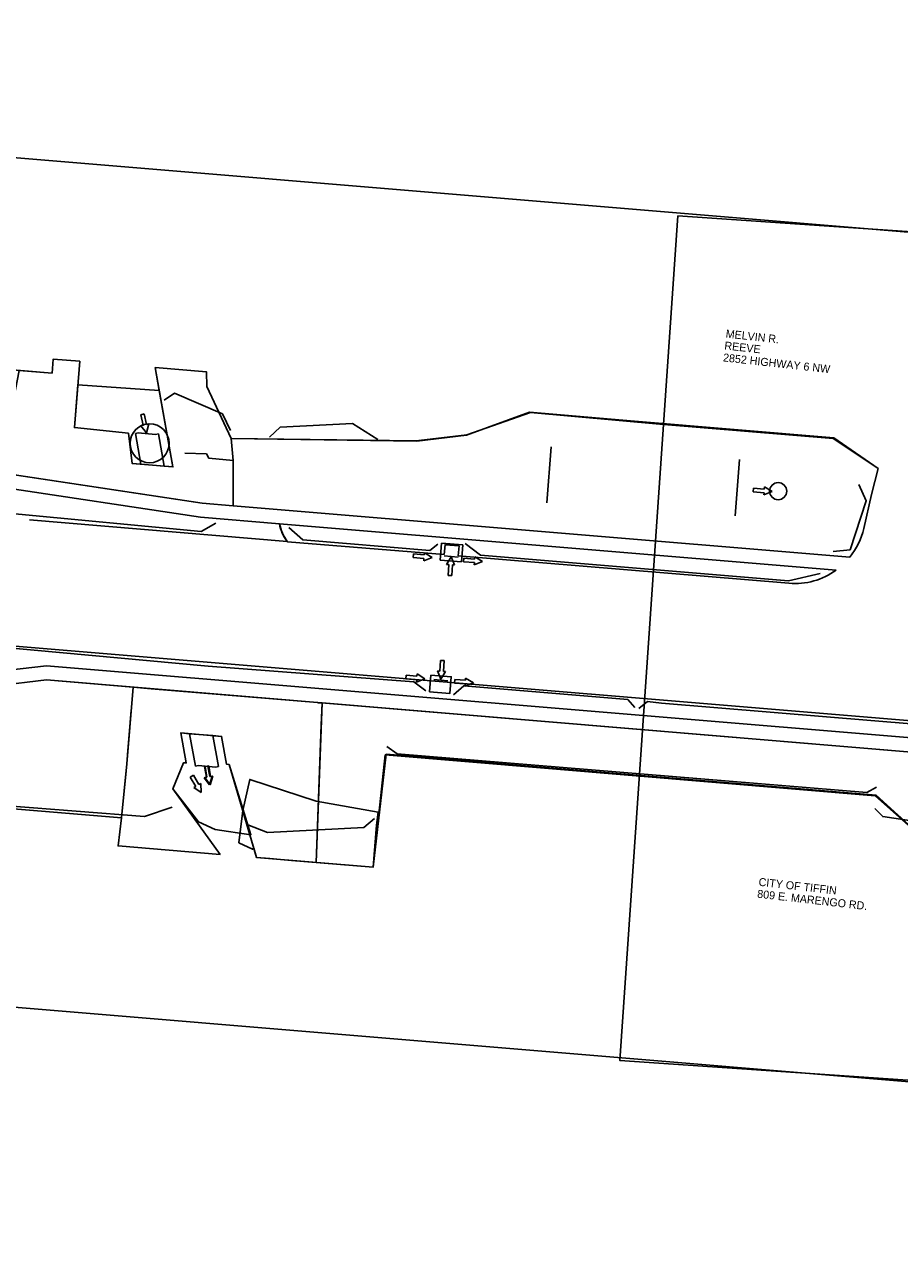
# Model space of a CAD drawing. Extents: x 20499990 to 20505779, y 7953198 to 7954399.
# Drawn here: x 20503807.3 to 20504117.2, y 7953486.1 to 7953917.4 of the extents above; entities that cross this region are included whole.
import ezdxf

# ---------------------------------------------------------------- set-up
doc = ezdxf.new("R2010")
doc.units = 0
for name, color, linetype in [('Building', 7, 'Continuous'), ('ClearGrub', 7, 'Continuous'), ('dsnCellElements', 7, 'Continuous'), ('ErosionControl', 7, 'Continuous'), ('NamedBoundary', 7, 'Continuous'), ('Seeding', 7, 'Continuous'), ('Text', 7, 'Continuous')]:
    doc.layers.add(name, color=color, linetype=linetype)

msp = doc.modelspace()

# ---------------------------------------------------------------- linework, layer by layer
at = {"layer": 'Building'}
for p, q in [((20503869.7, 7953742.74), (20503631.86, 7953778.64)), ((20503880.46, 7953770.66), (20503881.17, 7953762.87)), ((20503881.17, 7953762.87), (20503881.17, 7953746.8)), ((20503881.17, 7953746.8), (20504099.61, 7953728.58)), ((20503809.08, 7953741.78), (20503900.39, 7953734.16)), ((20503897.62, 7953740.41), (20503869.7, 7953742.74)), ((20503897.62, 7953740.41), (20504094.74, 7953723.96)), ((20503955.95, 7953729.53), (20503900.49, 7953734.03)), ((20504078.05, 7953719.34), (20503960.93, 7953729.11)), ((20503625.39, 7953668.38), (20503815.08, 7953690.11)), ((20503815.08, 7953690.11), (20504247.14, 7953654.05)), ((20503815.16, 7953685.08), (20503635.14, 7953664.47)), ((20503845.78, 7953682.53), (20503815.16, 7953685.08)), ((20503845.07, 7953673.92), (20503845.78, 7953682.53)), ((20504142.52, 7953657.76), (20503912.79, 7953676.94)), ((20503844.4, 7953665.62), (20503844.99, 7953672.96)), ((20503845.07, 7953673.92), (20503845.07, 7953673.92)), ((20503845.07, 7953673.92), (20503845.07, 7953673.92)), ((20503935.36, 7953658.74), (20503935.36, 7953658.74)), ((20503935.36, 7953658.74), (20503935.36, 7953658.74)), ((20503935.36, 7953658.74), (20503935.36, 7953658.74))]:
    msp.add_line(p, q, dxfattribs=at)
for points in [[(20504109.65, 7953759.97), (20504093.91, 7953770.89), (20504023.3, 7953776.79), (20503986.14, 7953780), (20503963.88, 7953771.82), (20503946.28, 7953769.64), (20503880.46, 7953770.66)], [(20504104.51, 7953738.74), (20504107.23, 7953750.76), (20504109.65, 7953759.97)], [(20504427.73, 7953645), (20504246.09, 7953660.16), (20503289.64, 7953739.98)], [(20503960.93, 7953729.11), (20503961.22, 7953732.6), (20503956.24, 7953733.01), (20503955.95, 7953729.53)], [(20503372.47, 7953675.36), (20503841.67, 7953636.21)], [(20503912.79, 7953676.94), (20503910.63, 7953620.42), (20503930.78, 7953618.73), (20503935.36, 7953658.74)], [(20503843.94, 7953660.06), (20503844.4, 7953665.62)], [(20503843.56, 7953655.35), (20503843.94, 7953660.06)], [(20503935.36, 7953658.74), (20503935.36, 7953658.74)], [(20503935.36, 7953658.74), (20503935.36, 7953658.74)], [(20503935.36, 7953658.74), (20503935.36, 7953658.74), (20504108.89, 7953644.26), (20504139.58, 7953616.36), (20504141.32, 7953644.33)], [(20503843.06, 7953650.36), (20503843.56, 7953655.35)], [(20503841.67, 7953636.21), (20503843.06, 7953650.36)]]:
    msp.add_lwpolyline(points, dxfattribs=at)
for centre, radius, start, end in [((20503912.74, 7953743.37), 15.4, 191.0582, 216.7042), ((20503911.41, 7953742.77), 13.99, 189.7033, 218.6642), ((20504080.13, 7953744.25), 25, 321.1743, 347.268), ((20504080.13, 7953744.25), 25, 265.2301, 305.7659), ((20503873.4, 7953671.13), 28.46, 174.3633, 176.3018)]:
    msp.add_arc(centre, radius, start, end, dxfattribs=at)
at = {"layer": 'ClearGrub'}
msp.add_lwpolyline([(20503910.61, 7953642.15), (20503932.58, 7953638.18), (20503932.03, 7953633.68), (20503930.78, 7953618.73), (20503901.88, 7953621.15), (20503897.94, 7953621.47), (20503894.2, 7953621.79), (20503889.46, 7953622.18), (20503888.51, 7953625.46), (20503888.01, 7953625.1), (20503883.27, 7953627.4), (20503884.67, 7953638.82), (20503887.1, 7953649.86)], close=True, dxfattribs=at)
at = {"layer": 'dsnCellElements'}
for p, q in [((20503848.48, 7953779.04), (20503849.72, 7953779.32)), ((20503848.48, 7953779.04), (20503849.72, 7953779.32)), ((20503849.32, 7953775.32), (20503848.48, 7953779.04)), ((20503849.32, 7953775.32), (20503848.48, 7953779.04)), ((20503849.72, 7953779.32), (20503850.56, 7953775.59)), ((20503849.72, 7953779.32), (20503850.56, 7953775.59)), ((20503848.54, 7953775.14), (20503849.32, 7953775.32)), ((20503848.54, 7953775.14), (20503849.32, 7953775.32)), ((20503850.57, 7953772.66), (20503848.54, 7953775.14)), ((20503850.57, 7953772.66), (20503848.54, 7953775.14)), ((20503850.56, 7953775.59), (20503851.34, 7953775.77)), ((20503850.56, 7953775.59), (20503851.34, 7953775.77)), ((20503851.34, 7953775.77), (20503850.57, 7953772.66)), ((20503851.34, 7953775.77), (20503850.57, 7953772.66)), ((20504065.4, 7953751.71), (20504065.5, 7953752.98)), ((20504065.5, 7953752.98), (20504069.3, 7953752.7)), ((20504069.3, 7953752.7), (20504069.36, 7953753.49)), ((20504069.36, 7953753.49), (20504072.11, 7953751.85)), ((20504069.21, 7953751.43), (20504065.4, 7953751.71)), ((20504072.11, 7953751.85), (20504069.15, 7953750.63)), ((20504069.15, 7953750.63), (20504069.21, 7953751.43)), ((20503944.96, 7953728.46), (20503945.08, 7953729.73)), ((20503948.76, 7953728.11), (20503944.96, 7953728.46)), ((20503945.08, 7953729.73), (20503948.88, 7953729.38)), ((20503951.67, 7953728.48), (20503948.69, 7953727.32)), ((20503948.69, 7953727.32), (20503948.76, 7953728.11)), ((20503948.88, 7953729.38), (20503948.95, 7953730.17)), ((20503948.95, 7953730.17), (20503951.67, 7953728.48)), ((20503956.8, 7953726.01), (20503958.42, 7953728.76)), ((20503958.42, 7953728.76), (20503959.65, 7953725.81)), ((20503962.84, 7953726.93), (20503962.94, 7953728.2)), ((20503966.65, 7953726.65), (20503962.84, 7953726.93)), ((20503962.94, 7953728.2), (20503966.74, 7953727.91)), ((20503969.55, 7953727.07), (20503966.59, 7953725.85)), ((20503966.59, 7953725.85), (20503966.65, 7953726.65)), ((20503966.74, 7953727.91), (20503966.8, 7953728.71)), ((20503966.8, 7953728.71), (20503969.55, 7953727.07)), ((20503957.59, 7953725.95), (20503956.8, 7953726.01)), ((20503957.33, 7953722.14), (20503957.59, 7953725.95)), ((20503958.6, 7953722.06), (20503957.33, 7953722.14)), ((20503958.86, 7953725.87), (20503958.6, 7953722.06)), ((20503959.65, 7953725.81), (20503958.86, 7953725.87)), ((20503954.39, 7953688.22), (20503954.67, 7953692.02)), ((20503954.67, 7953692.02), (20503955.94, 7953691.93)), ((20503955.94, 7953691.93), (20503955.66, 7953688.12)), ((20503954.81, 7953685.32), (20503953.6, 7953688.28)), ((20503953.6, 7953688.28), (20503954.39, 7953688.22)), ((20503956.45, 7953688.06), (20503954.81, 7953685.32)), ((20503955.66, 7953688.12), (20503956.45, 7953688.06)), ((20503942.42, 7953685.45), (20503942.52, 7953686.72)), ((20503946.22, 7953685.13), (20503942.42, 7953685.45)), ((20503942.52, 7953686.72), (20503946.32, 7953686.4)), ((20503949.12, 7953685.53), (20503946.15, 7953684.34)), ((20503946.15, 7953684.34), (20503946.22, 7953685.13)), ((20503946.32, 7953686.4), (20503946.39, 7953687.2)), ((20503946.39, 7953687.2), (20503949.12, 7953685.53)), ((20503959.56, 7953683.97), (20503959.66, 7953685.24)), ((20503963.37, 7953683.69), (20503959.56, 7953683.97)), ((20503959.66, 7953685.24), (20503963.47, 7953684.96)), ((20503966.27, 7953684.11), (20503963.31, 7953682.89)), ((20503963.31, 7953682.89), (20503963.37, 7953683.69)), ((20503963.47, 7953684.96), (20503963.52, 7953685.75)), ((20503963.52, 7953685.75), (20503966.27, 7953684.11)), ((20503871.05, 7953654.36), (20503872.3, 7953654.59)), ((20503871.73, 7953650.61), (20503871.05, 7953654.36)), ((20503871.34, 7953654.41), (20503872.59, 7953654.61)), ((20503871.94, 7953650.64), (20503871.34, 7953654.41)), ((20503872.3, 7953654.59), (20503872.98, 7953650.83)), ((20503872.59, 7953654.61), (20503873.2, 7953650.85)), ((20503866.04, 7953650.68), (20503867.14, 7953651.32)), ((20503867.95, 7953647.38), (20503866.04, 7953650.68)), ((20503867.14, 7953651.32), (20503869.05, 7953648.01)), ((20503870.95, 7953650.46), (20503871.73, 7953650.61)), ((20503872.87, 7953647.9), (20503870.95, 7953650.46)), ((20503871.16, 7953650.52), (20503871.94, 7953650.64)), ((20503873.02, 7953647.92), (20503871.16, 7953650.52)), ((20503873.77, 7953650.98), (20503872.87, 7953647.9)), ((20503872.98, 7953650.83), (20503873.77, 7953650.98)), ((20503873.98, 7953650.97), (20503873.02, 7953647.92)), ((20503873.2, 7953650.85), (20503873.98, 7953650.97)), ((20503867.26, 7953646.98), (20503867.95, 7953647.38)), ((20503869.93, 7953645.22), (20503867.26, 7953646.98)), ((20503869.05, 7953648.01), (20503869.74, 7953648.41)), ((20503869.74, 7953648.41), (20503869.93, 7953645.22))]:
    msp.add_line(p, q, dxfattribs=at)
at = {"layer": 'ErosionControl'}
for p, q in [((20503855.01, 7953787.67), (20503826.26, 7953789.65)), ((20503859.9, 7953760.55), (20503855.01, 7953787.67)), ((20503848.56, 7953761.5), (20503846.58, 7953772.44)), ((20503854.74, 7953772.28), (20503856.81, 7953760.81)), ((20503881.17, 7953762.87), (20503880.46, 7953770.66)), ((20503992.26, 7953747.78), (20503993.79, 7953767.72)), ((20503845.46, 7953761.75), (20503848.56, 7953761.5)), ((20503848.56, 7953761.5), (20503856.81, 7953760.81)), ((20503881.24, 7953746.8), (20503881.17, 7953762.87)), ((20504059.04, 7953743.25), (20504060.57, 7953763.19)), ((20503800.57, 7953758.23), (20503870.28, 7953747.71)), ((20503856.81, 7953760.81), (20503859.9, 7953760.55)), ((20503856.81, 7953760.81), (20503859.9, 7953760.55)), ((20503870.28, 7953747.71), (20503881.24, 7953746.8)), ((20503960.89, 7953728.61), (20503955.91, 7953729.03)), ((20503952.26, 7953685.2), (20503957.24, 7953684.8)), ((20503845.78, 7953682.53), (20503843.56, 7953655.35)), ((20503852.24, 7953681.99), (20503845.78, 7953682.53)), ((20503845.78, 7953682.53), (20503845.78, 7953682.53)), ((20503911.07, 7953677.08), (20503852.24, 7953681.99)), ((20503911.07, 7953677.08), (20503911.07, 7953677.08)), ((20503911.07, 7953677.08), (20503911.07, 7953677.08)), ((20503911.07, 7953677.08), (20503911.07, 7953677.08)), ((20503912.44, 7953669.15), (20503912.79, 7953676.94)), ((20503862.69, 7953666.3), (20503865.78, 7953666.04)), ((20503865.78, 7953666.04), (20503862.69, 7953666.3)), ((20503862.69, 7953666.3), (20503865.78, 7953666.04)), ((20503865.78, 7953666.04), (20503867.85, 7953654.57)), ((20503874.04, 7953665.35), (20503865.78, 7953666.04)), ((20503865.78, 7953666.04), (20503867.85, 7953654.57)), ((20503876.01, 7953654.41), (20503874.04, 7953665.35)), ((20503874.04, 7953665.35), (20503877.13, 7953665.09)), ((20503876.01, 7953654.41), (20503874.04, 7953665.35)), ((20503874.04, 7953665.35), (20503877.13, 7953665.09)), ((20503843.56, 7953655.37), (20503843.56, 7953655.35))]:
    msp.add_line(p, q, dxfattribs=at)
for points in [[(20503826.97, 7953797.99), (20503817.52, 7953798.78), (20503817.1, 7953793.79), (20503805.48, 7953794.76), (20503803, 7953781.9), (20503802.76, 7953774.63), (20503802.16, 7953770.12)], [(20503855.01, 7953787.67), (20503859.9, 7953760.55), (20503845.46, 7953761.75), (20503844.1, 7953772.5), (20503824.99, 7953774.5), (20503826.97, 7953797.99)], [(20503880.46, 7953770.66), (20503871.92, 7953789.05), (20503871.77, 7953794.25), (20503853.64, 7953795.76), (20503855.01, 7953787.67)], [(20503859.9, 7953760.55), (20503855.01, 7953787.67), (20503826.26, 7953789.65), (20503824.99, 7953774.5), (20503844.1, 7953772.5), (20503845.46, 7953761.75), (20503848.56, 7953761.5)], [(20503826.26, 7953789.65), (20503824.99, 7953774.5), (20503844.1, 7953772.5), (20503845.46, 7953761.75)], [(20503856.78, 7953784.24), (20503860.5, 7953786.67), (20503877.39, 7953779.37), (20503880.26, 7953773.5)], [(20503894.14, 7953771.06), (20503897.86, 7953774.64), (20503923.5, 7953775.96), (20503932.4, 7953770.26)], [(20503846.58, 7953772.44), (20503847.57, 7953772.62), (20503853.76, 7953772.1), (20503854.74, 7953772.28)], [(20503881.17, 7953762.87), (20503872.61, 7953763.61), (20503871.73, 7953765.14), (20503864.1, 7953765.45)], [(20504093.66, 7953730.6), (20504099.7, 7953731.21), (20504105.4, 7953748.53), (20504102.82, 7953754.31)], [(20503799, 7953747.79), (20503802.78, 7953744.01), (20503869.88, 7953737.71), (20503875.04, 7953740.68)], [(20503900.91, 7953739.08), (20503905.84, 7953734.73), (20503950.84, 7953730.95), (20503953.7, 7953733.24)], [(20503963.32, 7953733.47), (20503968.82, 7953729.34), (20504077.83, 7953720.18), (20504089.05, 7953722.82)], [(20503949.49, 7953681.28), (20503945.16, 7953684.46), (20503872.39, 7953690.02), (20503799.21, 7953696.72), (20503792.9, 7953695.34)], [(20504023.41, 7953675.28), (20504020.94, 7953678.19), (20503962.9, 7953682.96), (20503959.19, 7953679.78)], [(20504159.22, 7953663.7), (20504155.57, 7953666.68), (20504091.33, 7953672.01), (20504032.85, 7953676.87), (20504027.91, 7953677.4), (20504024.82, 7953675.01)], [(20503868.94, 7953634.85), (20503859.82, 7953646.47), (20503863.61, 7953655.66), (20503864.6, 7953655.7), (20503862.69, 7953666.3)], [(20503862.69, 7953666.3), (20503864.6, 7953655.7), (20503863.61, 7953655.66), (20503859.82, 7953646.47), (20503868.94, 7953634.85), (20503874.87, 7953632.12), (20503887.49, 7953630.23), (20503879.79, 7953655.09), (20503878.91, 7953655.22), (20503877.13, 7953665.09), (20503874.04, 7953665.35)], [(20503868.94, 7953634.85), (20503859.82, 7953646.47), (20503863.61, 7953655.66), (20503864.6, 7953655.7), (20503862.69, 7953666.3)], [(20503876.58, 7953623.26), (20503859.82, 7953646.47), (20503863.61, 7953655.66), (20503864.6, 7953655.7), (20503862.69, 7953666.3), (20503877.13, 7953665.09), (20503878.91, 7953655.22), (20503879.79, 7953655.09), (20503889.46, 7953622.18)], [(20503912.11, 7953662.68), (20503912.44, 7953669.15)], [(20503877.13, 7953665.09), (20503878.91, 7953655.22), (20503879.79, 7953655.09), (20503887.49, 7953630.23)], [(20503877.13, 7953665.09), (20503878.91, 7953655.22), (20503879.79, 7953655.09), (20503887.49, 7953630.23)], [(20503889.46, 7953622.18), (20503910.63, 7953620.42), (20503912.11, 7953662.68)], [(20503912.11, 7953662.68), (20503912.11, 7953662.68)], [(20503935.65, 7953661.47), (20503939.24, 7953658.92), (20504105.65, 7953645.17), (20504109.07, 7953647.15)], [(20503843.56, 7953655.35), (20503841.67, 7953636.21), (20503840.45, 7953626.27), (20503876.58, 7953623.26)], [(20503867.85, 7953654.57), (20503868.84, 7953654.74), (20503875.03, 7953654.23), (20503876.01, 7953654.41)], [(20503867.85, 7953654.57), (20503868.84, 7953654.74), (20503875.03, 7953654.23), (20503876.01, 7953654.41)], [(20503723.64, 7953649.88), (20503728.66, 7953646.17), (20503849.78, 7953636.69), (20503859.63, 7953640.03)], [(20503886.38, 7953633.79), (20503893.35, 7953630.98), (20503927.47, 7953632.82), (20503931.25, 7953635.98)], [(20504108.45, 7953639.59), (20504111.27, 7953636.67), (20504127.63, 7953634.23), (20504133.38, 7953636.08)], [(20503887.49, 7953630.23), (20503874.87, 7953632.12), (20503868.94, 7953634.85)], [(20503887.49, 7953630.23), (20503874.87, 7953632.12), (20503868.94, 7953634.85)]]:
    msp.add_lwpolyline(points, dxfattribs=at)
for points in [[(20503955, 7953733.54), (20503954.53, 7953727.56), (20503962.07, 7953726.96), (20503962.55, 7953732.94)], [(20503951.24, 7953686.78), (20503958.47, 7953686.21), (20503958, 7953680.31), (20503950.78, 7953680.88)]]:
    msp.add_lwpolyline(points, close=True, dxfattribs=at)
for centre, radius in [((20503851.64, 7953768.93), 6.92), ((20504074.22, 7953751.96), 3.04)]:
    msp.add_circle(centre, radius, dxfattribs=at)
msp.add_arc((20503913.17, 7953691.85), 14.92, 261.9009, 268.5586, dxfattribs=at)
at = {"layer": 'NamedBoundary'}
for points in [[(20503238.22, 7953917.37), (20503213.27, 7953618.41), (20504150.52, 7953540.19), (20504175.47, 7953839.15)], [(20504038.63, 7953849.54), (20504018.15, 7953550.24), (20504956.36, 7953486.07), (20504976.83, 7953785.37)]]:
    msp.add_lwpolyline(points, close=True, dxfattribs=at)
at = {"layer": 'Seeding'}
for p, q in [((20503632.44, 7953783.61), (20503870.28, 7953747.71)), ((20503869.7, 7953742.74), (20503631.86, 7953778.64)), ((20503881.17, 7953762.87), (20503880.46, 7953770.66)), ((20503880.46, 7953770.66), (20503881.17, 7953762.87)), ((20503848.56, 7953761.5), (20503856.81, 7953760.81)), ((20503881.24, 7953746.8), (20503881.17, 7953762.87)), ((20503881.17, 7953762.87), (20503881.17, 7953746.8)), ((20503856.81, 7953760.81), (20503859.9, 7953760.55)), ((20503870.28, 7953747.71), (20503881.24, 7953746.8)), ((20503881.17, 7953746.8), (20504099.61, 7953728.58)), ((20503809.08, 7953741.78), (20503900.39, 7953734.16)), ((20503897.62, 7953740.41), (20503869.7, 7953742.74)), ((20503897.62, 7953740.41), (20504094.74, 7953723.96)), ((20503955.95, 7953729.53), (20503900.49, 7953734.03)), ((20504078.05, 7953719.34), (20503960.93, 7953729.11)), ((20503625.39, 7953668.38), (20503815.08, 7953690.11)), ((20503815.08, 7953690.11), (20504247.14, 7953654.05)), ((20503815.16, 7953685.08), (20503635.14, 7953664.47)), ((20504246.23, 7953649.11), (20503815.16, 7953685.08))]:
    msp.add_line(p, q, dxfattribs=at)
for points in [[(20503826.97, 7953797.99), (20503817.52, 7953798.78), (20503817.1, 7953793.79), (20503740.06, 7953800.22), (20503714.23, 7953802.38), (20503664.2, 7953806.55), (20503262.97, 7953840.03), (20503262.23, 7953832.05)], [(20503853.64, 7953795.76), (20503859.9, 7953760.55), (20503845.46, 7953761.75), (20503844.1, 7953772.5), (20503824.99, 7953774.5), (20503826.97, 7953797.99)], [(20503880.46, 7953770.66), (20503871.92, 7953789.05), (20503871.77, 7953794.25), (20503853.64, 7953795.76)], [(20503859.9, 7953760.55), (20503855.01, 7953787.67), (20503826.26, 7953789.65), (20503824.99, 7953774.5), (20503844.1, 7953772.5), (20503845.46, 7953761.75), (20503848.56, 7953761.5)], [(20504109.65, 7953759.97), (20504093.7, 7953770.68), (20504032.31, 7953775.75), (20503986.55, 7953779.79), (20503963.98, 7953771.92), (20503945.86, 7953769.75), (20503880.46, 7953770.66)], [(20503881.17, 7953762.87), (20503872.61, 7953763.61), (20503871.73, 7953765.14), (20503864.1, 7953765.45)], [(20504104.51, 7953738.74), (20504107.23, 7953750.76), (20504109.65, 7953759.97)], [(20504427.73, 7953645), (20504246.09, 7953660.16), (20503289.64, 7953739.98)], [(20503960.93, 7953729.11), (20503961.22, 7953732.6), (20503956.24, 7953733.01), (20503955.95, 7953729.53)], [(20503372.47, 7953675.36), (20503841.67, 7953636.21), (20503840.45, 7953626.27), (20503876.58, 7953623.26)], [(20503876.58, 7953623.26), (20503859.82, 7953646.47), (20503863.61, 7953655.66), (20503864.6, 7953655.7), (20503862.69, 7953666.3), (20503877.13, 7953665.09), (20503878.91, 7953655.22), (20503879.79, 7953655.09), (20503889.46, 7953622.18)], [(20503889.46, 7953622.18), (20503930.78, 7953618.73), (20503935.07, 7953658.52), (20504108.6, 7953644.04), (20504139.58, 7953616.36), (20504139.32, 7953591.3), (20504148.2, 7953590.56)]]:
    msp.add_lwpolyline(points, dxfattribs=at)
for centre, radius, start, end in [((20503911.35, 7953742.75), 13.93, 189.6718, 218.0905), ((20503912.74, 7953743.37), 15.4, 191.0582, 217.3094), ((20504080.13, 7953744.25), 25, 321.1743, 347.268), ((20504080.13, 7953744.25), 25, 265.2301, 305.7659)]:
    msp.add_arc(centre, radius, start, end, dxfattribs=at)

# ---------------------------------------------------------------- texts
at = {"layer": 'Text'}
for s, height, rotation, p in [('MELVIN R. ', 2.835, 353.6591, (20504055.52, 7953806.43)), ('REEVE', 2.835, 353.6591, (20504055.05, 7953802.21)), ('2852 HIGHWAY 6 NW', 2.8346, 353.6591, (20504054.58, 7953797.98)), ('CITY OF TIFFIN', 2.8346, 353.4901, (20504067.16, 7953612.19)), ('809 E. MARENGO RD.', 2.8346, 353.4901, (20504066.68, 7953607.97))]:
    msp.add_text(s, height=height, rotation=rotation, dxfattribs=at).set_placement(p)

doc.saveas('drawing.dxf')
